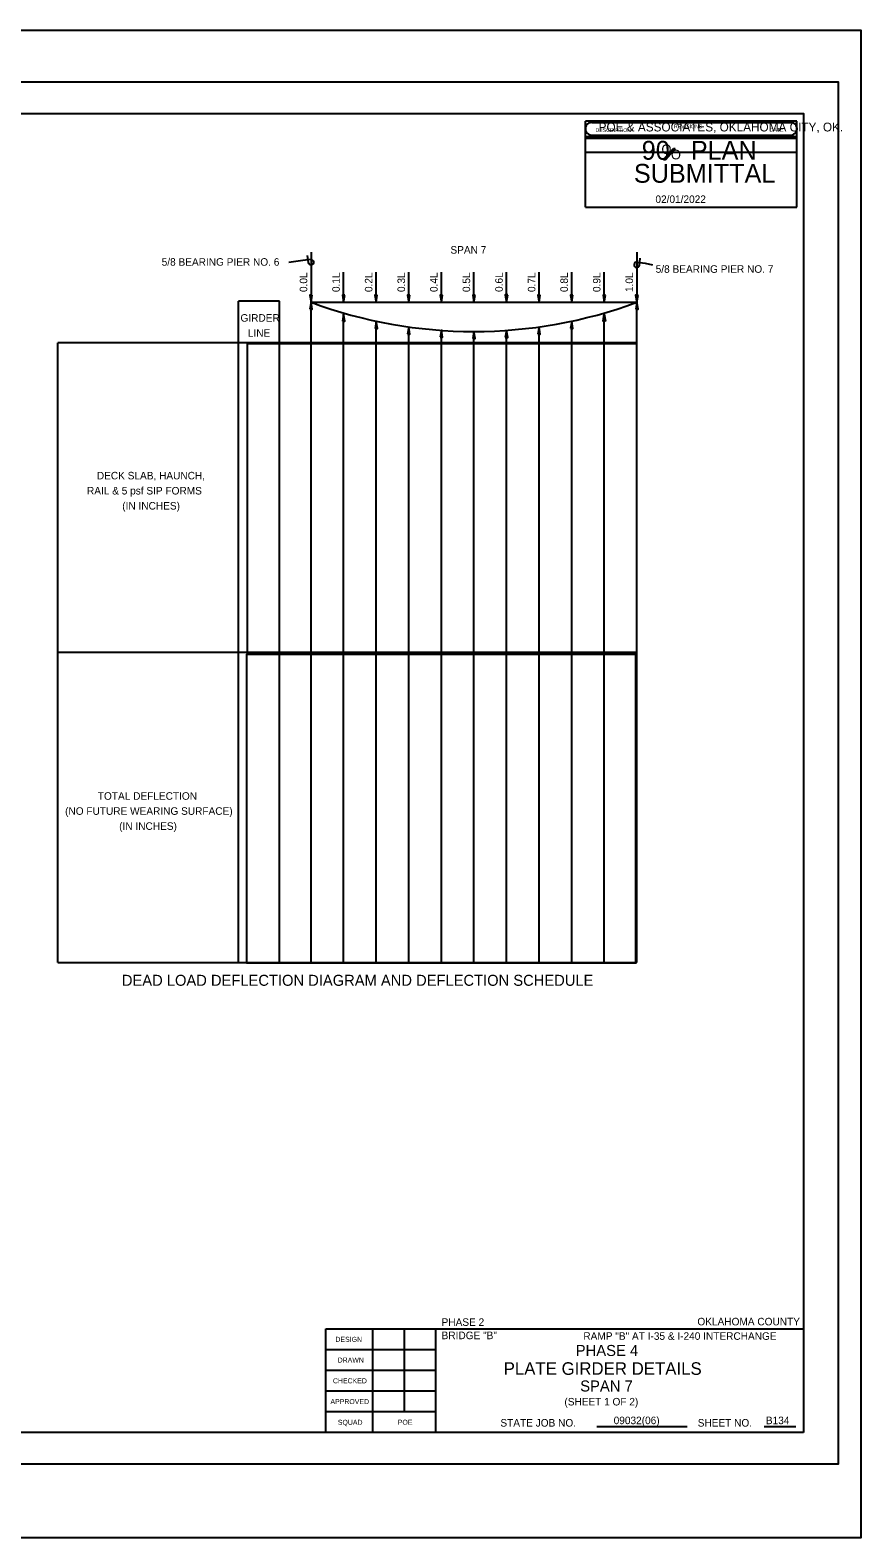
# Model space of a CAD drawing. Extents: x 4944 to 17449, y 3824 to 49087.
# Drawn here: x 10699 to 11968, y 21053 to 23357 of the extents above; entities that cross this region are included whole.
import ezdxf

# ---------------------------------------------------------------- set-up
doc = ezdxf.new("R2010")
doc.units = 0
for name, color, linetype in [('1', 7, 'Continuous'), ('36_S_LINES', 7, 'Continuous'), ('37_S_TXT', 7, 'Continuous'), ('3A', 7, 'Continuous'), ('6', 7, 'Continuous'), ('BEAM', 7, 'Continuous'), ('DIM', 7, 'Continuous'), ('ID', 7, 'Continuous'), ('Level 14', 7, 'Continuous'), ('Level 17', 7, 'Continuous'), ('Level 27', 7, 'Continuous'), ('Level 34', 7, 'Continuous'), ('Level 36', 7, 'Continuous'), ('REVISED', 7, 'Continuous')]:
    doc.layers.add(name, color=color, linetype=linetype)

# ---------------------------------------------------------------- blocks, each defined once
blk = doc.blocks.new('DWG010')
at = {"layer": '1'}
for p, q in [((0, 0.047), (0.141, 0.047)), ((0.047, 0), (0.047, 0.125))]:
    blk.add_line(p, q, dxfattribs=at)
blk.add_arc((0, 0), 0.0469, 90, 0, dxfattribs=at)
blk = doc.blocks.new('ARROWH')
at = {"layer": '1'}
blk.add_lwpolyline([(0.123, -0.021), (0.123, 0.021), (-0.002, 0)], close=True, dxfattribs=at)

msp = doc.modelspace()

# ---------------------------------------------------------------- linework, layer by layer
at = {"layer": '36_S_LINES'}
for p, q in [((11115.7, 23005.2), (11094.2, 23002.5)), ((11638.4, 23001.4), (11649.9, 22998.7)), ((11178, 22941.7), (11178, 22987.6)), ((11227.8, 22941.7), (11227.8, 22987.6)), ((11277.5, 22941.7), (11277.5, 22987.6)), ((11327.3, 22941.7), (11327.3, 22987.6)), ((11377.1, 22941.7), (11377.1, 22987.6)), ((11426.8, 22941.9), (11426.8, 22987.7)), ((11476.6, 22941.7), (11476.6, 22987.6)), ((11526.4, 22941.7), (11526.4, 22987.6)), ((11576.2, 22941.7), (11576.2, 22987.6)), ((11128.2, 21932.7), (11128.2, 22942.4)), ((11625.9, 21932.7), (11625.9, 22942.4)), ((11178, 21932.7), (11178, 22923.1)), ((11227.8, 21932.7), (11227.8, 22912.4)), ((11277.5, 21932.7), (11277.5, 22903.6)), ((11476.6, 21932.7), (11476.6, 22903.6)), ((11526.4, 21932.7), (11526.4, 22912.4)), ((11576.2, 21932.7), (11576.2, 22923.1)), ((11327.3, 21932.7), (11327.3, 22898.5)), ((11377.1, 21932.7), (11377.1, 22896.9)), ((11426.8, 21932.7), (11426.8, 22898.5))]:
    msp.add_line(p, q, dxfattribs=at)
at = {"layer": '37_S_TXT'}
msp.add_lwpolyline([(8512, 23357.4), (11968.1, 23357.4), (11968.1, 21053.4), (8512, 21053.4)], close=True, dxfattribs=at)
at = {"layer": '3A'}
for p, q in [((11128.2, 23018.1), (11128.2, 22941.7)), ((11625.9, 23018.1), (11625.9, 22941.7))]:
    msp.add_line(p, q, dxfattribs=at)
for points in [[(11030.9, 22406.9), (11625.9, 22406.9), (11625.9, 22878), (11030.9, 22878)], [(11029.6, 21932.2), (11624.6, 21932.2), (11624.6, 22403.2), (11029.6, 22403.2)]]:
    msp.add_lwpolyline(points, close=True, dxfattribs=at)
at = {"layer": '6'}
for p, q in [((11128.2, 22941.7), (11128.2, 22941.7)), ((11178, 22941.7), (11178, 22941.7)), ((11227.8, 22941.7), (11227.8, 22941.7)), ((11277.5, 22941.7), (11277.5, 22941.7)), ((11327.3, 22941.7), (11327.3, 22941.7)), ((11377.1, 22941.7), (11377.1, 22941.7)), ((11426.8, 22941.7), (11426.8, 22941.7)), ((11476.6, 22941.7), (11476.6, 22941.7)), ((11526.4, 22941.7), (11526.4, 22941.7)), ((11576.2, 22941.7), (11576.2, 22941.7)), ((11625.9, 22941.7), (11625.9, 22941.7))]:
    msp.add_line(p, q, dxfattribs=at)
at = {"layer": 'BEAM'}
msp.add_arc((11377.1, 23610.7), 713.8, 249.5951, 290.4049, dxfattribs=at)
at = {"layer": 'DEFPOINTS'}
for p, q in [((11870.5, 23218.3), (11547.4, 23218.3)), ((11547.4, 23170.3), (11547.4, 23218.3)), ((11870.5, 23170.3), (11870.5, 23218.3)), ((11870.5, 23194.3), (11547.4, 23194.3)), ((11870.5, 23170.3), (11547.4, 23170.3))]:
    msp.add_line(p, q, dxfattribs=at)
at = {"layer": 'DIM'}
msp.add_lwpolyline([(8669.2, 23278.2), (11933.3, 23278.2), (11933.3, 21166.2), (8669.2, 21166.2)], close=True, dxfattribs=at)
at = {"layer": 'Level 14'}
for p, q in [((11150.9, 21214.2), (11150.9, 21372.6)), ((11150.9, 21372.6), (11880.5, 21372.6)), ((11318.8, 21214.2), (11318.8, 21372.7)), ((11318.8, 21214.2), (11318.8, 21372.7))]:
    msp.add_line(p, q, dxfattribs=at)
msp.add_lwpolyline([(11880.5, 21214.2), (8856.4, 21214.2), (8856.4, 23230.2), (11880.5, 23230.2)], close=True, dxfattribs=at)
at = {"layer": 'Level 17'}
for p, q in [((11222.8, 21214.2), (11222.8, 21372.7)), ((11270.8, 21245.9), (11270.8, 21372.7)), ((11564.7, 21223.4), (11703, 21223.4)), ((11564.7, 21223.4), (11703, 21223.4)), ((11820.5, 21223.4), (11868.7, 21223.4)), ((11820.5, 21223.4), (11868.7, 21223.4))]:
    msp.add_line(p, q, dxfattribs=at)
for points in [[(11318.8, 21340.9), (11150.9, 21340.9)], [(11318.8, 21309.2), (11150.9, 21309.2)], [(11318.8, 21277.5), (11150.9, 21277.5)], [(11318.8, 21245.9), (11150.9, 21245.9)]]:
    msp.add_lwpolyline(points, dxfattribs=at)
at = {"layer": 'Level 27'}
msp.add_line((11128.2, 22941.7), (11625.9, 22941.7), dxfattribs=at)
at = {"layer": 'Level 34'}
for p, q in [((11017.6, 21932.7), (11017.6, 22943.3)), ((11080.2, 22943.3), (11017.6, 22943.3)), ((11080.2, 21932.7), (11080.2, 22943.3)), ((10741.7, 21932.7), (10741.7, 22879.8)), ((11625.9, 22879.8), (10741.7, 22879.8)), ((11625.9, 21932.7), (11625.9, 22879.8)), ((10741.7, 22406.9), (11625.9, 22406.9)), ((10741.7, 21932.7), (11625.9, 21932.7))]:
    msp.add_line(p, q, dxfattribs=at)
at = {"layer": 'Level 36'}
for p, q in [((11557, 23216.3), (11860.9, 23216.3)), ((11547.4, 23192.3), (11870.5, 23192.3)), ((11547.4, 23086.8), (11547.4, 23192.3)), ((11557, 23197.1), (11860.9, 23197.1)), ((11870.5, 23086.8), (11870.5, 23192.3)), ((11666.8, 23159.8), (11681.7, 23176.4)), ((11666.8, 23159.8), (11669.7, 23159.8)), ((11668.5, 23159.8), (11683.4, 23176.4)), ((11669, 23159.8), (11683.9, 23176.4)), ((11669.7, 23159.8), (11684.6, 23176.4)), ((11681.7, 23176.4), (11684.6, 23176.4)), ((11547.4, 23086.8), (11870.5, 23086.8))]:
    msp.add_line(p, q, dxfattribs=at)
for centre, start, end in [((11557, 23206.7), 89.9952, 270), ((11861, 23206.7), 270, 90.0048)]:
    msp.add_arc(centre, 9.6, start, end, dxfattribs=at)

# ---------------------------------------------------------------- block references
at = {"layer": '36_S_LINES'}
for name, p, xscale, yscale, rotation in [('DWG010', (11128.2, 23002.7), 85.92279574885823, -85.92279574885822, -172.8686111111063), ('DWG010', (11625.9, 22998.9), 85.92279574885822, 85.92279574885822, -7.131388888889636), ('ARROWH', (11128.2, 22941.9), 85.9227957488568, 85.9227957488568, 90), ('ARROWH', (11178, 22941.9), 85.9227957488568, 85.9227957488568, 90), ('ARROWH', (11227.7, 22941.9), 85.9227957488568, 85.9227957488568, 90), ('ARROWH', (11277.5, 22941.9), 85.9227957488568, 85.9227957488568, 90), ('ARROWH', (11327.3, 22941.9), 85.9227957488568, 85.9227957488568, 90), ('ARROWH', (11377, 22941.9), 85.9227957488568, 85.9227957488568, 90), ('ARROWH', (11426.8, 22942.1), 85.9227957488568, 85.9227957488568, 90), ('ARROWH', (11476.6, 22941.9), 85.9227957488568, 85.9227957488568, 90), ('ARROWH', (11526.4, 22941.9), 85.9227957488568, 85.9227957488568, 90), ('ARROWH', (11576.1, 22941.9), 85.9227957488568, 85.9227957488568, 90), ('ARROWH', (11625.9, 22941.9), 85.9227957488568, 85.9227957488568, 90), ('ARROWH', (11128.2, 22941.6), 85.92279574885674, 85.92279574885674, -90.00000000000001), ('ARROWH', (11626, 22941.6), 85.92279574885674, 85.92279574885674, -90.00000000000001), ('ARROWH', (11178, 22923), 85.92279574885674, 85.92279574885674, -90.00000000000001), ('ARROWH', (11227.8, 22912.2), 85.92279574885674, 85.92279574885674, -90.00000000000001), ('ARROWH', (11277.6, 22903.5), 85.92279574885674, 85.92279574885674, -90.00000000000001), ('ARROWH', (11476.6, 22903.5), 85.92279574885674, 85.92279574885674, -90.00000000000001), ('ARROWH', (11526.4, 22912.2), 85.92279574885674, 85.92279574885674, -90.00000000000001), ('ARROWH', (11576.1, 22923), 85.92279574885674, -85.92279574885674, -90.00000000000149), ('ARROWH', (11327.3, 22898.8), 85.92279574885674, 85.92279574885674, -90.00000000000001), ('ARROWH', (11377.1, 22896.8), 85.92279574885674, 85.92279574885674, -90.00000000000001), ('ARROWH', (11426.8, 22898.3), 85.92279574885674, 85.92279574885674, -90.00000000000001)]:
    msp.add_blockref(name, p, dxfattribs=dict(at, xscale=xscale, yscale=yscale, rotation=rotation))

# ---------------------------------------------------------------- texts
at = {"layer": '3A'}
for s, height, p in [('SPAN 7', 11.52, (11341.2, 23015.9)), ('5/8 BEARING PIER NO. 6', 11.52, (10900.1, 22997.4)), ('5/8 BEARING PIER NO. 7', 11.52, (11654.7, 22986.6)), ('GIRDER', 11.52, (11020.5, 22911.9)), ('LINE', 11.52, (11031.7, 22888.9)), ('DECK SLAB, HAUNCH,', 11.52, (10801.1, 22670.9)), ('RAIL & 5 psf SIP FORMS', 11.52, (10786, 22647.8)), ('(IN INCHES)', 11.52, (10839.9, 22624.8)), ('TOTAL DEFLECTION', 11.52, (10802.6, 22181.3)), ('(NO FUTURE WEARING SURFACE)', 11.52, (10752.6, 22158.3)), ('(IN INCHES)', 11.52, (10835.2, 22135.3)), ('PHASE 2', 11.52, (11327.7, 21377.3)), ('OKLAHOMA COUNTY', 11.52, (11718.4, 21378.1)), ('BRIDGE "B"', 11.52, (11327.7, 21357)), ('RAMP "B" AT I-35 & I-240 INTERCHANGE', 11.52, (11544.2, 21356)), ('(SHEET 1 OF 2)', 11.5, (11515.3, 21255.7)), ('09032(06)', 11.52, (11590.5, 21227.1)), ('B134', 11.52, (11823, 21227.1))]:
    msp.add_text(s, height=height, dxfattribs=at).set_placement(p)
for s, p in [('0.0L', (11122.5, 22957.2)), ('0.1L', (11172.2, 22957.2)), ('0.2L', (11222, 22957.2)), ('0.3L', (11271.8, 22957.2)), ('0.4L', (11321.6, 22957.2)), ('0.5L', (11371.3, 22957.2)), ('0.6L', (11421.1, 22957.3)), ('0.7L', (11470.9, 22957.2)), ('0.8L', (11520.6, 22957.2)), ('0.9L', (11570.4, 22957.2)), ('1.0L', (11620.1, 22957.2))]:
    msp.add_text(s, height=11.52, rotation=90, dxfattribs=at).set_placement(p)
at = {"layer": 'BEAM'}
for s, height, p in [('DEAD LOAD DEFLECTION DIAGRAM AND DEFLECTION SCHEDULE', 16.8, (10839.3, 21897)), ('PLATE GIRDER DETAILS', 19.2, (11422.5, 21302.5))]:
    msp.add_text(s, height=height, dxfattribs=at).set_placement(p)
at = {"layer": 'DEFPOINTS'}
for s, height, p in [('DESCRIPTION', 5.76, (11562.7, 23201.8)), ('REVISIONS', 5.76, (11682.6, 23207.5)), ('DATE', 5.76, (11828.6, 23202.2)), ('PHASE 4', 16.88, (11532.6, 21331.3))]:
    msp.add_text(s, height=height, dxfattribs=at).set_placement(p)
at = {"layer": 'ID'}
msp.add_text('SPAN 7', height=16.88, dxfattribs=at).set_placement((11539.4, 21277))
at = {"layer": 'Level 36'}
for s, height, p in [('POE & ASSOCIATES, OKLAHOMA CITY, OK.', 13.44, (11567.6, 23202.6)), ('90   PLAN', 28.8, (11633.4, 23159.4)), ('O', 14.7, (11663.5, 23168)), ('O', 14.7, (11678, 23159.9)), ('SUBMITTAL', 28.8, (11621.4, 23124.2)), ('02/01/2022', 11.52, (11654.3, 23093.3))]:
    msp.add_text(s, height=height, dxfattribs=at).set_placement(p)
at = {"layer": 'REVISED'}
for s, height, p in [('DESIGN', 7.68, (11165.5, 21352.9)), ('DRAWN', 7.68, (11168.9, 21321.2)), ('CHECKED', 7.68, (11161.7, 21289.5)), ('APPROVED', 7.68, (11157.9, 21257.8)), ('SQUAD', 7.68, (11169.2, 21226.1)), ('POE', 7.68, (11260.8, 21226.2)), ('STATE JOB NO.', 11.52, (11417.5, 21223.4)), ('STATE JOB NO.', 11.52, (11417.5, 21223.4)), ('SHEET NO. ', 11.52, (11718.9, 21223.4)), ('SHEET NO. ', 11.52, (11718.9, 21223.4))]:
    msp.add_text(s, height=height, dxfattribs=at).set_placement(p)

doc.saveas('drawing.dxf')
